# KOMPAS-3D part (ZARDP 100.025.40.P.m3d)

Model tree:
1. Операция без истории:1
2. Операция без истории:2
3. Операция без истории:3
4. Операция без истории:4
5. Операция без истории:5
6. Операция без истории:6
7. Операция без истории:7
8. Операция без истории:8
9. Операция без истории:9
10. Операция без истории:10
11. Операция без истории:11
12. Операция без истории:12
13. Операция без истории:13
14. Операция без истории:14
15. Операция без истории:15
16. Операция без истории:16
17. Операция без истории:17
18. Операция без истории:18
19. Операция без истории:19
20. Операция без истории:20
21. Операция без истории:21
22. Операция без истории:22
23. Операция без истории:23
24. Операция без истории:24
25. Операция без истории:25
26. Операция без истории:26
27. Операция без истории:27
28. Операция без истории:28
29. Операция без истории:29
30. Операция без истории:30
31. Операция без истории:31
32. Операция без истории:32
33. Операция без истории:33
34. Операция без истории:34
35. Операция без истории:35

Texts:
  ЗАРДП 100.025.40-XX.Р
